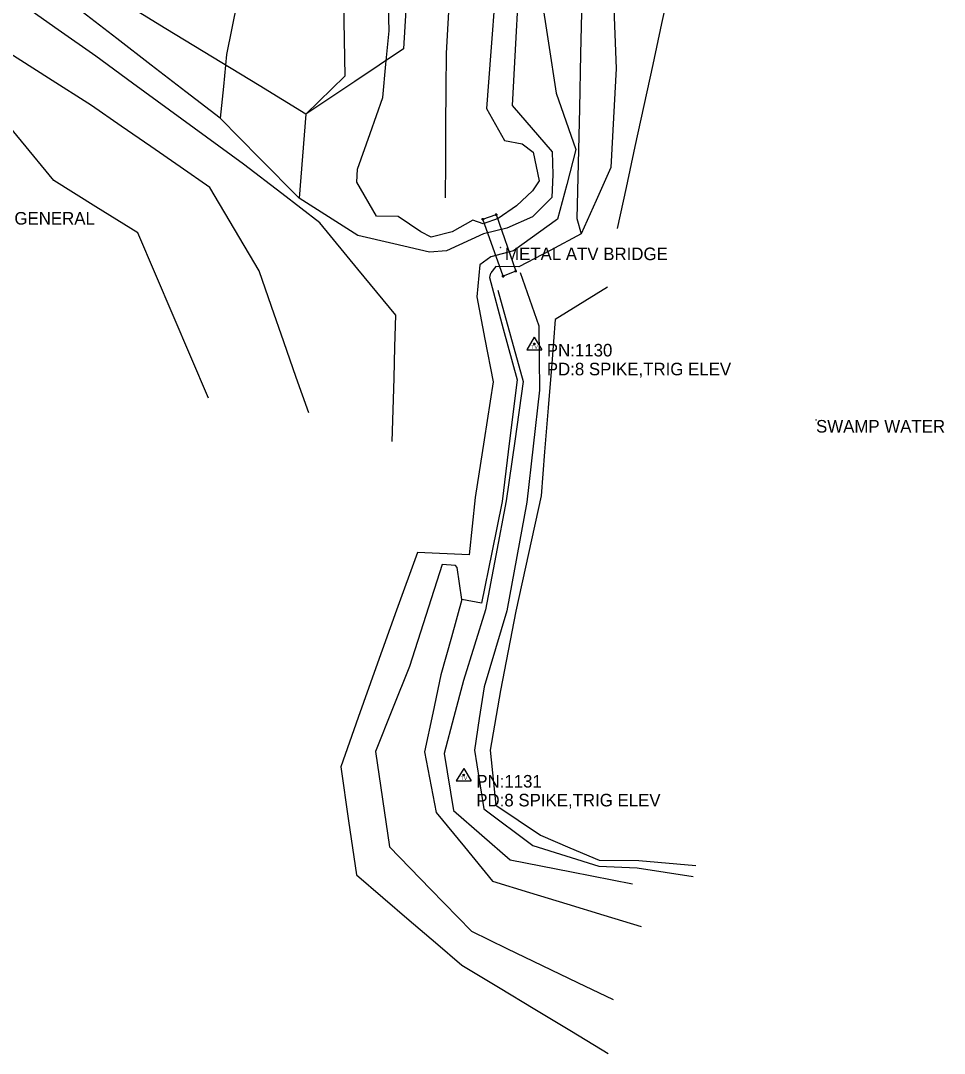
# Model space of a CAD drawing. Extents: x 1445297 to 1476720, y 2042269 to 2057889.
# Drawn here: x 1446184.7 to 1446551.6, y 2055123.7 to 2055534.2 of the extents above; entities that cross this region are included whole.
import ezdxf

# ---------------------------------------------------------------- set-up
doc = ezdxf.new("R2010")
doc.units = 0
for name, color, linetype in [('S_BRIDGE', 7, 'Continuous'), ('S_DITCHLINE', 7, 'Continuous'), ('S_LEVEE', 7, 'Continuous'), ('S_MSC_PT_SYM', 7, 'Continuous'), ('S_SECONDARY_CTL', 7, 'Continuous'), ('S_SECONDARY_CTL_ANNOT', 7, 'Continuous'), ('S_STR_PT_SYM', 7, 'Continuous'), ('S_STREAM', 7, 'Continuous'), ('S_SURVEY_TEXT_ANNOT', 7, 'Continuous'), ('S_TREE', 7, 'Continuous'), ('S_UTILITY_POLE_ANNOT', 7, 'Continuous')]:
    doc.layers.add(name, color=color, linetype=linetype)

msp = doc.modelspace()

# ---------------------------------------------------------------- linework, layer by layer
at = {"layer": 'S_BRIDGE'}
for p, q in [((1446368.29, 2055455.23), (1446373.6, 2055457.11)), ((1446376.36, 2055432.58), (1446368.29, 2055455.23)), ((1446373.6, 2055457.11), (1446381.31, 2055434.68)), ((1446381.31, 2055434.68), (1446376.36, 2055432.58))]:
    msp.add_line(p, q, dxfattribs=at)
at = {"layer": 'S_DITCHLINE'}
for points in [[(1446318.36, 2055774.56), (1446312.27, 2055750.48), (1446306.19, 2055726.4), (1446300.11, 2055702.32), (1446294.03, 2055678.24), (1446298.47, 2055658.52), (1446302.92, 2055638.8), (1446307.36, 2055619.09), (1446311.81, 2055599.37), (1446312.23, 2055577.56), (1446312.65, 2055555.76), (1446313.08, 2055533.95), (1446313.5, 2055512.14), (1446297.96, 2055497.05), (1446296.61, 2055480.35), (1446295.26, 2055463.64)], [(1446391.31, 2055545.08), (1446394.35, 2055525.22), (1446397.4, 2055505.36), (1446405.22, 2055482.92), (1446401.6, 2055469.12), (1446397.97, 2055455.32), (1446380.46, 2055442.66), (1446371.51, 2055440.38), (1446367.02, 2055437.17), (1446365.83, 2055424.48), (1446369.1, 2055407.54), (1446372.37, 2055390.61), (1446368.81, 2055367.64), (1446365.25, 2055344.67), (1446362.82, 2055321.88), (1446342.28, 2055322.81), (1446333.99, 2055299.86), (1446325.7, 2055276.91), (1446318.76, 2055257.28), (1446311.82, 2055237.65), (1446314.92, 2055216.15), (1446318.02, 2055194.64), (1446328.49, 2055185.68), (1446338.96, 2055176.72), (1446349.43, 2055167.76), (1446359.89, 2055158.8), (1446374.43, 2055150.03), (1446388.96, 2055141.26), (1446403.5, 2055132.49), (1446418.03, 2055123.72)], [(1446332.29, 2055366.96), (1446332.65, 2055379.51), (1446333.01, 2055392.06), (1446333.36, 2055404.6), (1446333.72, 2055417.15), (1446318.65, 2055435.46), (1446303.58, 2055453.78), (1446288.39, 2055465.49), (1446273.2, 2055477.21), (1446258.52, 2055487.91), (1446243.84, 2055498.61), (1446229.16, 2055509.32), (1446214.49, 2055520.02), (1446199.6, 2055530.55), (1446184.71, 2055541.08)], [(1446382.34, 2055544.75), (1446381.11, 2055522.59), (1446379.88, 2055500.43), (1446395.87, 2055482.07), (1446396.08, 2055473.08), (1446395.68, 2055463.89), (1446387.95, 2055456.22), (1446377.86, 2055451.68), (1446368.52, 2055449.43), (1446353.83, 2055442.65), (1446347.14, 2055442.16), (1446332.86, 2055445.47), (1446318.58, 2055448.78), (1446306.92, 2055456.21), (1446295.26, 2055463.64), (1446279.62, 2055479.51), (1446263.98, 2055495.38), (1446250.28, 2055505.95), (1446236.58, 2055516.52), (1446222.88, 2055527.1), (1446209.18, 2055537.67)], [(1446270.72, 2055541.69), (1446266.42, 2055520.69), (1446265.2, 2055508.04), (1446263.98, 2055495.38)], [(1446407.56, 2055542.91), (1446407.08, 2055521.07), (1446406.61, 2055499.24), (1446406.13, 2055477.41), (1446405.66, 2055455.57), (1446407.34, 2055449.45)], [(1446299.1, 2055378.25), (1446294.17, 2055392.37), (1446289.24, 2055406.49), (1446284.31, 2055420.62), (1446279.38, 2055434.74), (1446269.61, 2055451.33), (1446259.85, 2055467.93), (1446248.1, 2055476.05), (1446236.35, 2055484.18), (1446224.6, 2055492.31), (1446212.84, 2055500.44), (1446195.69, 2055511.4), (1446178.54, 2055522.35), (1446163.75, 2055526.02), (1446148.96, 2055529.68), (1446131.24, 2055537.2)], [(1446259.32, 2055384.16), (1446252.31, 2055400.58), (1446245.29, 2055417), (1446238.28, 2055433.42), (1446231.27, 2055449.85), (1446214.57, 2055460.26), (1446197.87, 2055470.68), (1446184.97, 2055486.27), (1446172.06, 2055501.87)], [(1446359.88, 2055304.17), (1446355.76, 2055289.17), (1446351.65, 2055274.17), (1446348.38, 2055258.89), (1446345.12, 2055243.62), (1446349.78, 2055219.42), (1446360.95, 2055205.81), (1446372.11, 2055192.2), (1446386.86, 2055187.67), (1446401.61, 2055183.14), (1446416.35, 2055178.61), (1446431.1, 2055174.08)]]:
    msp.add_lwpolyline(points, dxfattribs=at)
at = {"layer": 'S_LEVEE'}
for points in [[(1446355.08, 2055545.05), (1446353.66, 2055521.31), (1446353.56, 2055506.91), (1446353.47, 2055492.51), (1446353.38, 2055478.11), (1446353.29, 2055463.71)], [(1446383.15, 2055434.15), (1446390.57, 2055412.86), (1446390.67, 2055400.07), (1446390.76, 2055387.28), (1446388.27, 2055365.04), (1446385.78, 2055342.8), (1446381.8, 2055321.22), (1446377.83, 2055299.64), (1446373.3, 2055284.55), (1446368.77, 2055269.45), (1446366.86, 2055256.81), (1446364.95, 2055244.17), (1446368.63, 2055220.86), (1446388.17, 2055206.35), (1446401.29, 2055202.23), (1446414.41, 2055198.1), (1446429.57, 2055197.43), (1446451.88, 2055193.97)], [(1446374.21, 2055427.02), (1446379.27, 2055408.92), (1446384.34, 2055390.82), (1446380.96, 2055367.05), (1446377.58, 2055343.28), (1446373.45, 2055321.61), (1446369.31, 2055299.95), (1446364.92, 2055285.95), (1446360.53, 2055271.95), (1446356.73, 2055257.45), (1446352.94, 2055242.95), (1446356.68, 2055220.24), (1446367.89, 2055210.47), (1446379.1, 2055200.7), (1446403.43, 2055195.88), (1446427.76, 2055191.05)]]:
    msp.add_lwpolyline(points, dxfattribs=at)
at = {"layer": 'S_MSC_PT_SYM'}
for points in [[(1446375.23, 2055444), (1446375.23, 2055444.05), (1446375.23, 2055444), (1446375.18, 2055444), (1446375.23, 2055444), (1446375.23, 2055443.95), (1446375.23, 2055444), (1446375.28, 2055444)], [(1446500.63, 2055375.47), (1446500.63, 2055375.52), (1446500.63, 2055375.47), (1446500.58, 2055375.47), (1446500.63, 2055375.47), (1446500.63, 2055375.42), (1446500.63, 2055375.47), (1446500.68, 2055375.47)]]:
    msp.add_lwpolyline(points, dxfattribs=at)
at = {"layer": 'S_SECONDARY_CTL'}
for p, q in [((1446388.69, 2055408.33), (1446385.68, 2055403.37)), ((1446388.69, 2055408.33), (1446391.64, 2055403.37)), ((1446385.68, 2055403.37), (1446391.64, 2055403.37)), ((1446360.66, 2055236.98), (1446357.65, 2055232.03)), ((1446360.66, 2055236.98), (1446363.6, 2055232.03)), ((1446357.65, 2055232.03), (1446363.6, 2055232.03))]:
    msp.add_line(p, q, dxfattribs=at)
for centre, radius in [((1446388.69, 2055405.72), 0.311), ((1446388.69, 2055405.72), 0.183), ((1446388.69, 2055405.72), 0.103), ((1446360.66, 2055234.37), 0.311), ((1446360.66, 2055234.37), 0.183), ((1446360.66, 2055234.37), 0.103)]:
    msp.add_circle(centre, radius, dxfattribs=at)
at = {"layer": 'S_STR_PT_SYM'}
for points in [[(1446368.29, 2055455.23), (1446368.29, 2055455.73), (1446368.29, 2055455.23), (1446367.79, 2055455.23), (1446368.29, 2055455.23), (1446368.29, 2055454.73), (1446368.29, 2055455.23), (1446368.79, 2055455.23)], [(1446373.6, 2055457.11), (1446373.6, 2055457.61), (1446373.6, 2055457.11), (1446373.1, 2055457.11), (1446373.6, 2055457.11), (1446373.6, 2055456.61), (1446373.6, 2055457.11), (1446374.1, 2055457.11)], [(1446381.31, 2055434.68), (1446381.31, 2055435.18), (1446381.31, 2055434.68), (1446380.81, 2055434.68), (1446381.31, 2055434.68), (1446381.31, 2055434.18), (1446381.31, 2055434.68), (1446381.81, 2055434.68)], [(1446376.36, 2055432.58), (1446376.36, 2055433.08), (1446376.36, 2055432.58), (1446375.86, 2055432.58), (1446376.36, 2055432.58), (1446376.36, 2055432.08), (1446376.36, 2055432.58), (1446376.86, 2055432.58)]]:
    msp.add_lwpolyline(points, dxfattribs=at)
at = {"layer": 'S_STREAM'}
for points in [[(1446373.16, 2055544.58), (1446371.43, 2055521.95), (1446369.71, 2055499.32), (1446376.9, 2055486.55), (1446383.83, 2055485.19), (1446388.21, 2055481.86), (1446390.64, 2055470.58), (1446387.94, 2055466.61), (1446381.62, 2055460.65), (1446374.36, 2055455.52), (1446368.45, 2055453.44), (1446364.23, 2055454.9), (1446356.02, 2055450.2), (1446347.71, 2055448.19), (1446343.59, 2055450.3), (1446334.68, 2055456.31), (1446325.98, 2055456.45), (1446318.26, 2055469.99), (1446318.54, 2055475.14), (1446323.51, 2055489.37), (1446328.48, 2055503.61), (1446329.77, 2055516.88), (1446331.06, 2055530.16), (1446330.44, 2055554.96)], [(1446420.19, 2055542.44), (1446420.72, 2055528.79), (1446421.24, 2055515.14), (1446420.17, 2055495.51), (1446419.1, 2055475.87), (1446413.22, 2055462.66), (1446407.34, 2055449.45), (1446394.96, 2055442.89), (1446382.59, 2055436.33), (1446373.39, 2055436.52), (1446371.45, 2055434.02)], [(1446371.34, 2055433.8), (1446370.96, 2055432.07), (1446376.4, 2055411.74), (1446381.85, 2055391.4), (1446378.91, 2055367.22), (1446375.97, 2055343.03), (1446371.85, 2055322.86), (1446367.73, 2055302.69), (1446359.88, 2055304.17), (1446358.04, 2055316.82), (1446357.35, 2055317.66), (1446352.15, 2055317.99), (1446345.61, 2055297.72), (1446339.08, 2055277.45), (1446332.38, 2055260.6), (1446325.68, 2055243.75), (1446328.43, 2055224.75), (1446331.17, 2055205.75), (1446347.47, 2055188.99), (1446363.76, 2055172.24), (1446377.82, 2055165.45), (1446391.87, 2055158.67), (1446405.93, 2055151.89), (1446419.98, 2055145.1)], [(1446417.81, 2055428.29), (1446397.04, 2055415.38), (1446395.63, 2055397.86), (1446394.21, 2055380.33), (1446392.79, 2055362.81), (1446391.38, 2055345.29), (1446386.37, 2055322.41), (1446381.36, 2055299.54), (1446378.33, 2055283.76), (1446375.3, 2055267.98), (1446371.21, 2055244.26), (1446373.37, 2055222.37), (1446391.2, 2055210.45), (1446402.81, 2055205.46), (1446414.43, 2055200.47), (1446430.23, 2055200.36), (1446452.82, 2055198.4)]]:
    msp.add_lwpolyline(points, dxfattribs=at)
at = {"layer": 'S_TREE'}
for points in [[(1446442.79, 2055549.39), (1446439.26, 2055533.08), (1446435.73, 2055516.77), (1446432.21, 2055500.47), (1446428.68, 2055484.16), (1446425.15, 2055467.85), (1446421.63, 2055451.55)], [(1446337.64, 2055538.53), (1446336.78, 2055523.02), (1446317.37, 2055510.04), (1446297.96, 2055497.05), (1446279.44, 2055508.36), (1446260.91, 2055519.68), (1446242.39, 2055530.99), (1446223.87, 2055542.3)]]:
    msp.add_lwpolyline(points, dxfattribs=at)

# ---------------------------------------------------------------- texts
at = {"layer": 'S_SECONDARY_CTL'}
for p in [(1446387.49, 2055403.7), (1446359.45, 2055232.36)]:
    msp.add_text('TV', height=1.5, dxfattribs=at).set_placement(p)
at = {"layer": 'S_SECONDARY_CTL_ANNOT'}
for s, p in [('PN:1130', (1446393.69, 2055400.72)), ('PD:8 SPIKE,TRIG ELEV', (1446393.69, 2055393.22)), ('PN:1131', (1446365.66, 2055229.37)), ('PD:8 SPIKE,TRIG ELEV', (1446365.66, 2055221.87))]:
    msp.add_text(s, height=5, dxfattribs=at).set_placement(p)
at = {"layer": 'S_SURVEY_TEXT_ANNOT'}
for s, p in [(' METAL ATV BRIDGE', (1446375.23, 2055439)), ('SWAMP WATER', (1446500.63, 2055370.47))]:
    msp.add_text(s, height=5, dxfattribs=at).set_placement(p)
at = {"layer": 'S_UTILITY_POLE_ANNOT'}
msp.add_text('FIBER OPTIC FROMGENERAL', height=5, dxfattribs=at).set_placement((1446118.68, 2055453.13))

doc.saveas('drawing.dxf')
